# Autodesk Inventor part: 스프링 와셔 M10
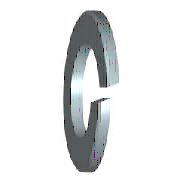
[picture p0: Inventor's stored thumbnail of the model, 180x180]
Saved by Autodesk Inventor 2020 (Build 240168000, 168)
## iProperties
Created: 2012-02
Part Number: 스프링 와셔 M10
Material: 강철, 연강
Description: 스프링 와셔
Document SubType Name: Modeling
Standard: JIS B 1251
Designer: mdu-01
Standards Organization: JIS
Language: ko-KR
Size Designation: 번호 2 10
Categories: <MemberInstance><Categories><Category DisplayName="조임쇠" InternalName="e4da775c-781d-43d5-af7c-5136215cf5a6" Mnemonic="FSTN"><Category DisplayName="와셔" InternalN
Density: 1 g/cm^3
Appearance: 강철
IsCustomPart: 1
Author: mdu-01
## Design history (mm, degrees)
sketch "스케치1"
  geometry: C1 r 9.2 at (0, 0); C2 r 5.1 at (0, 0); 1 further point
  constraints: 2 centre point, 2 coincident
  dimensions: "d0" = 10.2 diameter of C2 (= SD1); "d1" = 18.4 diameter of C1 (= SD2)
extrude "본체" new body sketch "스케치1" distance "d2" = 2.5 (= SD); taper "d3" = 0 deg
sketch "스케치2"
  geometry: L1 (0, -5.1)-(0, 5.1) reference; L2 (2.5, 9.2)-(2.5, -9.2) reference; L3 (-1.2, 0)-(7.2, 0) reference; L4 (0, -0.5)-(2.5, 0.41); L5 (0, 0.5)-(2.5, 1.41)
  constraints: 4 end point, 4 point on line, 1 parallel
  dimensions: "d4" = 0.5 distance from line of L3 L4.start (= 0.2 x SD); "d5" = 0.5 distance from line of L3 L5.start (= 0.2 x SD); "d6" = 70 deg angle of L2 L4 (= FAWI)
extrude "절단부" cut sketch "스케치2" stored distance "d7" = 2.5 (= SD); taper "d8" = 0 deg
workaxis "Work Axis1"
workplane "Work Plane1"
body "Solid1"
other parameters: "SD1" = 10.2 [user parameter; used in 1 equation term], "SD2" = 18.4 [user parameter; used in 1 equation term], "SD" = 2.5 [user parameter; used in 4 equation terms], "FAWI" = 70 deg [user parameter; used in 1 equation term], "d9" = 0, "d10" = 0, "d11" = 0, "d12" = 0, "SDI" = 3.7 [user parameter]
